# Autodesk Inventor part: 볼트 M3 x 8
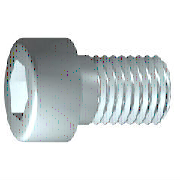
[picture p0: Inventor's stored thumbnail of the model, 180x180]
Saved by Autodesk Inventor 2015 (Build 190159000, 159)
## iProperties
IsCustomPart: 0
Created: 2012-02
Part Number: 볼트 M3 x 8
Material: 스테인리스강
Description: 6각 소켓 머리 캡 나사
Document SubType Name: Modeling
Standard: ISO 4762
Designer: mduedu
Standard Revision: Fourth edition 2004-03-01
Standards Organization: ISO
Language: ko-KR
Size Designation: M3 x 8
Categories: <MemberInstance><Categories><Category DisplayName="조임쇠" InternalName="e4da775c-781d-43d5-af7c-5136215cf5a6" Mnemonic="FSTN"><Category DisplayName="볼트" InternalN
Density: 8.08 g/cm^3
Appearance: 반광택
Author: mduedu
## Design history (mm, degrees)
sketch "스케치1"
  geometry: L1 (-0.867, 0)-(8, 0); L2 (8, 0)-(8, 1.5); L3 (8, 1.5)-(1.25, 1.5); L4 (1.25, 1.5)-(0.943, 1.5); L5 (0.943, 1.5)-(0, 1.5); L6 (0, 1.5)-(0, 2.75); L7 (0, 2.75)-(-3, 2.75); L8 (-3, 2.75)-(-3, 1.443); L9 (-3, 1.443)-(-1.7, 1.443); L10 (-1.7, 1.443)-(-0.867, 0); L11 (-5.2, 0)-(10.2, 0) reference; L12 (0, -0.55)-(0, 3.3) reference; L13 (1.25, 1.5)-(0, 1.5)
  constraints: 22 end point, 6 parallel, 2 collinear, 2 perpendicular, 1 horizontal, 1 point on line
  dimensions: "d1" = 6.75 distance from line of L3.end L2 (= GEL); "d2" = 0.30683 distance of L4.end L3.end (computed from GAL); "d3" = 3 distance between parallel lines of L8 L6 (= KOH); "d4" = 1.3 distance of L8.end L9.end (= INTI); "d5" = 60 deg angle of L10 L1; "d6" = 3 diameter of L3 L1 (= GD); "d7" = 3 diameter of L5 L1 (= BDM); "d8" = 2.88675 diameter of L9 L1 (= 1.1547 x SW); "d9" = 5.5 diameter of L7 L1 (= KOD); "d26" = 8 distance between parallel lines of L12 L2 (= NLG)
revolve "본체" sketch "스케치1" stored, may be unused: angle "d10" = 90 deg
sketch "스케치2"
  geometry: L1 (0, -3.85)-(0, 3.85) reference; L2 (-3.85, 0)-(3.85, 0) reference; L3 (1.443, 0)-(0.722, -1.25); L4 (0.722, -1.25)-(-0.722, -1.25); L5 (-0.722, -1.25)-(-1.443, 0); L6 (-1.443, 0)-(-0.722, 1.25); L7 (-0.722, 1.25)-(0.722, 1.25); L8 (0.722, 1.25)-(1.443, 0); 2 further points
  constraints: 12 end point, 1 coincident, 1 horizontal alignment, 1 point on line, 12 other
extrude "슬롯" join sketch "스케치2" stored distance "d11" = 10; taper "d12" = 0 deg
workplane "Work Plane1"
fillet "Fillet2" dims "d30" = 0.1 (= R)
body "Solid1"
fillet "모깎기1" dims "d17" = 0.3 (= RR)
feature "스레드" dims "d13" = 6.75 (= GEL), "d14" = 0
chamfer "모따기1" distance "d15" = 0.30673 (= -0.5 x SPD + 0.5 x GD); stored, may be unused: second distance "d16" = 0.30673 (= GUL), angle "d27" = 45 deg
other parameters: "GD" = 3 [user parameter; used in 2 equation terms], "NLG" = 8 [user parameter; used in 1 equation term], "GEL" = 6.75 [user parameter; used in 2 equation terms], "KOD" = 5.5 [user parameter; used in 1 equation term], "KOH" = 3 [user parameter; used in 1 equation term], "INTI" = 1.3 [user parameter; used in 1 equation term], "GAL" = 0.30673 (= 0.61345 x PTC) [user parameter; used in 1 equation term], "GUL" = 0.30673 (= 0.61345 x PTC) [user parameter; used in 1 equation term], "BDM" = 3 (= NND) [user parameter; used in 1 equation term], "SW" = 2.5 [user parameter; used in 2 equation terms], "RR" = 0.3 [user parameter; used in 1 equation term], "SPD" = 2.38655 (= NND - 1.2269 x PTC) [user parameter; used in 1 equation term], "d19" = 0, "d28" = 0, "d29" = 0, "R" = 0.1 [user parameter; used in 1 equation term], "TOA" = 30 deg [user parameter], "GD1" = 2.38655 (= THREADDIA - 1.2269 x PTC) [user parameter], "THREADDIA" = 3 [user parameter; used in 1 equation term], "FAWI" = 45 deg [user parameter], "PTC" = 0.5 [user parameter; used in 5 equation terms], "NND" = 3 [user parameter; used in 2 equation terms], "E0" = 2.8875 (= 1.155 x SW) [user parameter]
